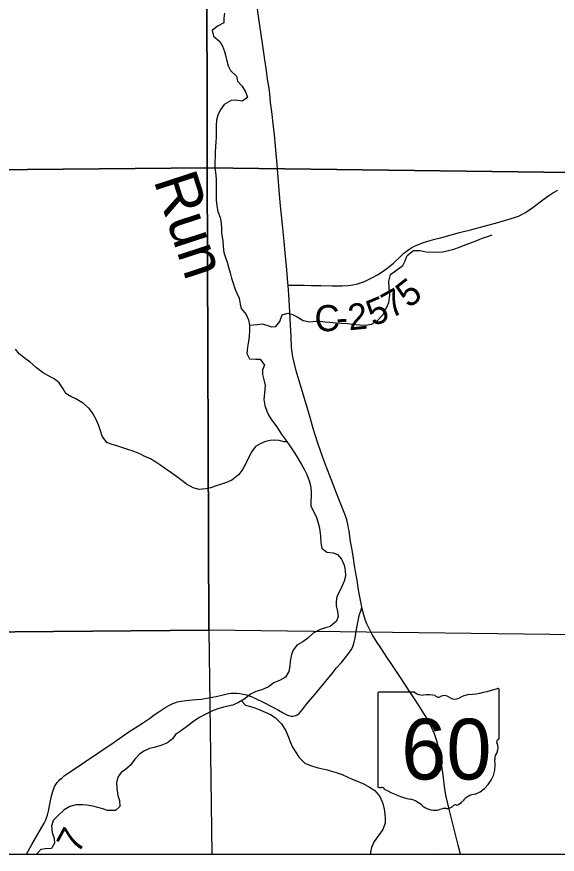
# Model space of a CAD drawing. Extents: x 0 to 34, y 0 to 22.
# Drawn here: x 2.657 to 3.831, y 18.268 to 20.086 of the extents above; entities that cross this region are included whole.
import ezdxf

# ---------------------------------------------------------------- set-up
doc = ezdxf.new("R2010")
doc.units = 0
for name, color, linetype in [('GM_X_County_Road', 7, 'Continuous'), ('GM_X_County_Road_Text', 7, 'Continuous'), ('GM_X_Interchange_Ramps', 7, 'Continuous'), ('GM_X_Major_River_Text', 7, 'Continuous'), ('GM_X_Section_Text', 7, 'Continuous'), ('GM_X_State_Route', 7, 'Continuous'), ('GM_X_Township_Road', 7, 'Continuous'), ('GM_X_Township_Road_Text', 7, 'Continuous'), ('GM_X_Township_Text', 7, 'Continuous'), ('SH_Text', 7, 'Continuous')]:
    doc.layers.add(name, color=color, linetype=linetype)

msp = doc.modelspace()

# ---------------------------------------------------------------- linework, layer by layer
at = {"layer": 'GM_X_County_Road'}
for p, q in [((3.5209, 18.6196), (3.4437, 18.6196)), ((3.7047, 18.5199), (3.7047, 18.6246)), ((3.4411, 18.6162), (3.4411, 18.4161)), ((3.7047, 18.5199), (3.7047, 18.5199))]:
    msp.add_line(p, q, dxfattribs=at)
for points in [[(3.4067, 18.8035), (3.4049, 18.8124), (3.4017, 18.8301), (3.3989, 18.8463), (3.3962, 18.863), (3.393, 18.882), (3.3908, 18.895), (3.3883, 18.9104), (3.3852, 18.9286), (3.3822, 18.9471), (3.3806, 18.9577), (3.3788, 18.9698), (3.3778, 18.9757), (3.376, 18.9848), (3.3736, 18.9937), (3.3708, 19.0025), (3.3654, 19.017), (3.3597, 19.0314), (3.3518, 19.0517), (3.3369, 19.0892), (3.327, 19.1154), (3.3173, 19.1416), (3.3103, 19.1622), (3.301, 19.1919), (3.2941, 19.2158), (3.2864, 19.2427), (3.2744, 19.2813), (3.2641, 19.3171), (3.2593, 19.3352), (3.2567, 19.3474), (3.2553, 19.3566), (3.254, 19.369), (3.2529, 19.3908), (3.251, 19.431), (3.2486, 19.4713), (3.2465, 19.5034), (3.2461, 19.5085), (3.2437, 19.5364), (3.2399, 19.5734), (3.2375, 19.5982), (3.2335, 19.6415), (3.2301, 19.6755), (3.2275, 19.7002), (3.2253, 19.7281), (3.2224, 19.765), (3.219, 19.8048), (3.2168, 19.8294), (3.2149, 19.8479), (3.2133, 19.8601), (3.2115, 19.8746), (3.2083, 19.9002), (3.2065, 19.9187), (3.205, 19.9309), (3.2027, 19.9463), (3.1984, 19.9739), (3.1957, 19.9923), (3.1915, 20.0231), (3.1846, 20.0724), (3.1759, 20.1339)], [(3.6208, 18.2679), (3.6156, 18.2875), (3.5967, 18.3628), (3.5924, 18.381), (3.5893, 18.3962), (3.5864, 18.4146), (3.583, 18.4392), (3.5788, 18.4699), (3.5763, 18.4852), (3.5739, 18.4973), (3.5709, 18.5093), (3.5682, 18.5182), (3.5651, 18.5269), (3.5615, 18.5355), (3.5562, 18.5466), (3.5474, 18.563), (3.5379, 18.5791), (3.5279, 18.5947), (3.5107, 18.6206), (3.4919, 18.6491), (3.4728, 18.6774), (3.461, 18.6956), (3.4493, 18.7138), (3.4372, 18.7318), (3.4288, 18.7449), (3.4223, 18.7579), (3.4176, 18.768), (3.4147, 18.7756), (3.4108, 18.7875), (3.4067, 18.8035)]]:
    msp.add_lwpolyline(points, dxfattribs=at)
for centre, radius, start, end in [((3.4441, 18.6166), 0.00305, 98.1301, 188.1301), ((3.5393, 18.6429), 0.0296, 231.6195, 271.1119), ((3.6108, 18.8925), 0.2796, 275.8445, 288.9065), ((3.7018, 18.625), 0.00294, 351.8621, 97.738), ((3.5491, 18.5073), 0.1064, 80.4867, 94.9883), ((3.5732, 18.6176), 0.00855, 219.7921, 297.1024), ((3.5858, 18.5945), 0.0178, 54.4667, 119.1411), ((3.6087, 18.6262), 0.0214, 233.8562, 294.8282), ((3.6465, 18.5585), 0.0563, 97.3462, 120.7689), ((3.704, 18.5122), 0.00454, 107.944, 210.337), ((3.6751, 18.499), 0.0273, 340.033, 23.6496), ((3.7016, 18.5195), 0.00314, 289.6038, 7.7341), ((3.6265, 18.4628), 0.0699, 292.3089, 8.9858), ((3.7152, 18.4761), 0.0198, 136.8065, 186.9296), ((3.4441, 18.4156), 0.00308, 171.9584, 258.3066), ((3.4446, 18.4361), 0.0235, 267.339, 280.6039), ((3.4494, 18.4045), 0.00848, 29.7484, 93.2717), ((3.5564, 18.5843), 0.2019, 240.4129, 257.1985), ((3.4962, 18.3262), 0.0632, 47.1842, 75.836), ((3.6074, 18.3967), 0.0226, 282.8732, 323.2771), ((3.656, 18.3599), 0.0383, 94.4031, 142.5768), ((3.5646, 18.4035), 0.0401, 230.7004, 286.2918), ((3.5877, 18.3343), 0.0329, 85.6951, 111.2099), ((3.5907, 18.3885), 0.0214, 268.777, 315.5493), ((3.61, 18.3692), 0.00601, 65.7517, 132.6484)]:
    msp.add_arc(centre, radius, start, end, dxfattribs=at)
at = {"layer": 'GM_X_County_Road_Text'}
for points in [[(3.108, 20.094), (3.1069, 20.0826), (3.1069, 20.0728), (3.0929, 20.0655), (3.0812, 20.056), (3.0843, 20.0435), (3.098, 20.0325), (3.1037, 20.0223), (3.108, 20.0102), (3.111, 19.9996), (3.1133, 19.9901), (3.1164, 19.9795), (3.121, 19.9692), (3.134, 19.9571), (3.1363, 19.9458), (3.1469, 19.9352), (3.1549, 19.9219), (3.1584, 19.9106), (3.1463, 19.9029), (3.133, 19.9048), (3.1228, 19.9043), (3.1077, 19.8956), (3.0986, 19.8834), (3.0938, 19.872), (3.0908, 19.8617), (3.0901, 19.8492), (3.0898, 19.8344), (3.0898, 19.8249), (3.0891, 19.8143), (3.0884, 19.8036), (3.088, 19.793), (3.0881, 19.7835), (3.0874, 19.7702), (3.0874, 19.7577), (3.0886, 19.7479), (3.0898, 19.7338), (3.0902, 19.7236), (3.0904, 19.6875), (3.0912, 19.6754), (3.0939, 19.6633), (3.0985, 19.6504), (3.1008, 19.6379), (3.1016, 19.6257), (3.102, 19.6151), (3.1044, 19.5999), (3.1056, 19.5874), (3.1071, 19.5745), (3.1106, 19.5635), (3.1137, 19.5533), (3.1168, 19.5423), (3.1206, 19.5302), (3.1237, 19.5184), (3.1268, 19.5078), (3.1306, 19.496), (3.1352, 19.4858), (3.1398, 19.4752), (3.1425, 19.4623), (3.1444, 19.4528), (3.1551, 19.4396), (3.1601, 19.4282), (3.1624, 19.4161), (3.1624, 19.4051), (3.1617, 19.3922)], [(3.1624, 19.4161), (3.1791, 19.418), (3.19, 19.4196), (3.2003, 19.4162), (3.2102, 19.4125), (3.22, 19.4137), (3.2287, 19.4247), (3.2335, 19.4391), (3.246, 19.4426), (3.2559, 19.4396), (3.2658, 19.4347), (3.2794, 19.4264), (3.2935, 19.4238), (3.3064, 19.425), (3.3158, 19.425), (3.3264, 19.4239), (3.3371, 19.4228), (3.35, 19.4217), (3.3621, 19.421), (3.3754, 19.4199), (3.386, 19.4185), (3.4023, 19.4174), (3.4152, 19.4167), (3.4273, 19.4186), (3.439, 19.4255), (3.4518, 19.4392), (3.4593, 19.4525), (3.4654, 19.4654), (3.4676, 19.4818), (3.466, 19.4969), (3.4655, 19.5117), (3.4685, 19.5262), (3.4957, 19.546), (3.5006, 19.5563), (3.5047, 19.5677), (3.5187, 19.5783), (3.5335, 19.5784), (3.546, 19.5754), (3.5687, 19.5747), (3.5816, 19.5759), (3.5949, 19.5783), (3.6062, 19.5813), (3.6187, 19.5859), (3.6308, 19.5909), (3.6414, 19.5948), (3.6566, 19.6005), (3.6664, 19.6047), (3.6796, 19.6093), (3.6898, 19.6128)], [(3.1617, 19.3922), (3.1606, 19.3819), (3.1584, 19.369), (3.157, 19.3546), (3.1627, 19.3432), (3.1763, 19.3429), (3.1858, 19.3426), (3.195, 19.3293), (3.1908, 19.3198), (3.1905, 19.3096), (3.1944, 19.2952), (3.1963, 19.2853), (3.1948, 19.269), (3.1938, 19.2553), (3.1957, 19.242), (3.1999, 19.2295), (3.2049, 19.2189), (3.2125, 19.2083), (3.2217, 19.1955), (3.2316, 19.1803), (3.24, 19.169), (3.2503, 19.1546), (3.2606, 19.1394), (3.2659, 19.1296), (3.2755, 19.1141), (3.2812, 19.1042), (3.2869, 19.0921), (3.2923, 19.0788), (3.295, 19.0682), (3.2966, 19.0553), (3.2966, 19.0447), (3.2955, 19.0344), (3.2959, 19.0238), (3.3005, 19.014), (3.3082, 18.9992), (3.3112, 18.9897), (3.3139, 18.9795), (3.3151, 18.97), (3.3167, 18.9583), (3.3175, 18.9438), (3.3194, 18.9321), (3.3308, 18.9238), (3.3441, 18.9219), (3.3536, 18.9189), (3.3624, 18.9083), (3.3681, 18.8958), (3.3704, 18.8845), (3.3712, 18.8716), (3.3682, 18.8609), (3.3637, 18.8503), (3.3585, 18.84), (3.3525, 18.8271), (3.3506, 18.8168), (3.351, 18.8073), (3.3534, 18.7948), (3.3549, 18.7838), (3.3516, 18.774), (3.338, 18.7621), (3.3277, 18.7594), (3.3149, 18.7548), (3.3009, 18.748), (3.2892, 18.7373), (3.2782, 18.7289), (3.2657, 18.7216), (3.2571, 18.711), (3.2537, 18.7015), (3.2511, 18.687), (3.2504, 18.6768), (3.2482, 18.6643), (3.2407, 18.6525), (3.2293, 18.6456), (3.2157, 18.6402), (3.204, 18.6315), (3.1896, 18.625), (3.176, 18.6211), (3.165, 18.6154), (3.1526, 18.6051), (3.1386, 18.5971), (3.1265, 18.5917), (3.1162, 18.589), (3.1064, 18.5874), (3.0939, 18.5836), (3.0822, 18.579), (3.0663, 18.571), (3.0538, 18.5645), (3.0417, 18.5565), (3.0289, 18.5465), (3.0145, 18.5362), (3.002, 18.5282), (2.9949, 18.5187), (2.9847, 18.5099), (2.9696, 18.5038), (2.9556, 18.4996), (2.9453, 18.4973), (2.9344, 18.4927), (2.9242, 18.4858), (2.9136, 18.474), (2.9034, 18.4603), (2.8932, 18.4519), (2.8834, 18.4454), (2.8762, 18.4352)], [(3.244, 19.1634), (3.2381, 19.1633), (3.2271, 19.1659), (3.2173, 19.1666), (3.2074, 19.1662), (3.1972, 19.1639), (3.1858, 19.1589), (3.1756, 19.1528), (3.1673, 19.1425), (3.1609, 19.1299), (3.1538, 19.1147), (3.1467, 19.1018), (3.1384, 19.0915), (3.124, 19.0801), (3.1127, 19.0747), (3.1017, 19.0713), (3.0881, 19.0667), (3.0782, 19.0636), (3.068, 19.0613), (3.0532, 19.0597), (3.0403, 19.0631), (3.0255, 19.0714), (3.0153, 19.0789), (3.0016, 19.0895), (2.9909, 19.097), (2.981, 19.1042), (2.9696, 19.1121), (2.9567, 19.1208), (2.9472, 19.1261), (2.9354, 19.1317), (2.9244, 19.137), (2.91, 19.1427), (2.9005, 19.146), (2.8876, 19.1505), (2.8743, 19.1547), (2.8622, 19.1584), (2.8527, 19.1618), (2.8424, 19.1754), (2.8386, 19.1868), (2.8355, 19.1982), (2.8305, 19.2103), (2.8217, 19.2258), (2.8141, 19.2356), (2.8019, 19.2466), (2.7856, 19.2568), (2.7742, 19.2617), (2.7639, 19.2681), (2.7575, 19.2783), (2.7494, 19.2916), (2.738, 19.2999), (2.7247, 19.307), (2.7141, 19.3131), (2.6997, 19.3236), (2.6856, 19.3372), (2.6761, 19.3437), (2.6624, 19.3542), (2.6544, 19.3644)], [(3.1452, 18.6009), (3.1537, 18.5918), (3.1647, 18.5884), (3.1742, 18.5854), (3.1849, 18.5813), (3.1966, 18.5764), (3.2084, 18.5711), (3.2183, 18.5651), (3.232, 18.5507), (3.2411, 18.536), (3.2473, 18.5223), (3.2511, 18.5121), (3.2557, 18.5007), (3.2622, 18.4905), (3.2706, 18.4776), (3.2828, 18.4655), (3.2953, 18.4607), (3.3089, 18.4565), (3.3184, 18.4539), (3.3309, 18.4509), (3.3408, 18.4483), (3.3511, 18.4457), (3.364, 18.4408), (3.3761, 18.4355), (3.3856, 18.431), (3.3951, 18.4273), (3.4088, 18.4212), (3.4213, 18.4152), (3.4346, 18.4065), (3.4456, 18.3933), (3.4518, 18.3778), (3.4548, 18.366), (3.4564, 18.3546), (3.4572, 18.3448), (3.4569, 18.3353), (3.4524, 18.3216), (3.4426, 18.3083), (3.4335, 18.2953), (3.4275, 18.2824), (3.4253, 18.2722), (3.4253, 18.2679)], [(2.8762, 18.4352), (2.8736, 18.423), (2.8741, 18.4109), (2.8768, 18.3957), (2.8799, 18.3847), (2.8811, 18.3718), (2.8712, 18.3627), (2.8542, 18.363), (2.8439, 18.3663), (2.8333, 18.3693), (2.8223, 18.372), (2.8094, 18.3746), (2.7996, 18.3749), (2.7863, 18.3748), (2.7719, 18.3714), (2.7602, 18.3645), (2.7459, 18.3515), (2.736, 18.3409), (2.7323, 18.3287), (2.7335, 18.3154), (2.7381, 18.3018), (2.7389, 18.2919), (2.7321, 18.2805), (2.7189, 18.2797), (2.709, 18.2782), (2.6999, 18.2679)]]:
    msp.add_lwpolyline(points, dxfattribs=at)
at = {"layer": 'GM_X_Interchange_Ramps'}
msp.add_lwpolyline([(2.6776, 18.2679), (2.6779, 18.2684), (2.6899, 18.2894), (2.7085, 18.3213), (2.7164, 18.3353), (2.72, 18.3424), (2.7219, 18.3472), (2.7234, 18.3524), (2.7256, 18.3615), (2.7288, 18.3767), (2.7326, 18.3948), (2.7351, 18.4042), (2.7374, 18.4108), (2.7392, 18.4148), (2.7418, 18.4194), (2.7446, 18.4236), (2.748, 18.4272), (2.7507, 18.43), (2.7554, 18.4339), (2.7602, 18.4379), (2.7673, 18.4431), (2.7883, 18.4572), (2.8064, 18.4691), (2.8372, 18.4901), (2.8684, 18.5114), (2.8985, 18.5319), (2.9142, 18.5421), (2.9321, 18.554), (2.9451, 18.5627), (2.9557, 18.5702), (2.9654, 18.5768), (2.9811, 18.5869), (2.989, 18.5916), (2.9945, 18.5944), (3.0002, 18.5967), (3.006, 18.5985), (3.0151, 18.6005), (3.0242, 18.6018), (3.0387, 18.6031), (3.0576, 18.6048), (3.0744, 18.6076), (3.0899, 18.6103), (3.1079, 18.6145), (3.1168, 18.6166), (3.1227, 18.6173), (3.1291, 18.6177), (3.1353, 18.6173), (3.1415, 18.6167), (3.1481, 18.6157), (3.156, 18.6137), (3.1658, 18.6105), (3.1904, 18.5988), (3.2149, 18.5867), (3.2255, 18.5809), (3.2345, 18.5757), (3.2425, 18.5714), (3.2472, 18.5693), (3.2506, 18.5683), (3.2535, 18.5679), (3.2567, 18.5678), (3.2599, 18.5682), (3.2629, 18.5693), (3.2658, 18.5706), (3.2685, 18.5723), (3.271, 18.5744), (3.2733, 18.577), (3.2778, 18.5823), (3.2867, 18.5935), (3.3045, 18.6149), (3.3146, 18.6271), (3.342, 18.6604), (3.3518, 18.6726), (3.3622, 18.6844), (3.3739, 18.6987), (3.3801, 18.7064), (3.3835, 18.7119), (3.3862, 18.717), (3.3886, 18.7231), (3.3901, 18.7283), (3.3922, 18.7373), (3.3945, 18.7524), (3.3969, 18.7675), (3.3998, 18.7815), (3.4015, 18.788), (3.4045, 18.7963), (3.4067, 18.8035)], dxfattribs=at)
at = {"layer": 'GM_X_State_Route'}
for points in [[(2.0472, 20.7772), (3.0692, 20.7682), (3.0705, 19.7579), (2.0531, 19.7487)], [(3.0692, 20.7682), (4.0731, 20.7603), (4.0736, 20.7285), (4.0835, 19.7451), (3.0705, 19.7579)], [(2.0531, 19.7487), (3.0705, 19.7579), (3.0743, 18.754), (2.0616, 18.746)], [(3.0705, 19.7579), (4.0835, 19.7451), (4.0839, 19.7307), (4.0999, 18.7413), (3.0743, 18.754)]]:
    msp.add_lwpolyline(points, close=True, dxfattribs=at)
msp.add_lwpolyline([(2.0795, 18.2679), (2.0616, 18.746), (3.0743, 18.754), (3.0806, 18.2679)], dxfattribs=at)
at = {"layer": 'GM_X_Township_Road'}
msp.add_lwpolyline([(3.2465, 19.5034), (3.2523, 19.5034), (3.265, 19.5032), (3.281, 19.5031), (3.2962, 19.5027), (3.3173, 19.5025), (3.342, 19.502), (3.3637, 19.5021), (3.3772, 19.5028), (3.3869, 19.5039), (3.3947, 19.5057), (3.4037, 19.5081), (3.4126, 19.5113), (3.4209, 19.5153), (3.4295, 19.5197), (3.4403, 19.5258), (3.4509, 19.5322), (3.4611, 19.5394), (3.4684, 19.5452), (3.4754, 19.5514), (3.4911, 19.5664), (3.4981, 19.5725), (3.5054, 19.5782), (3.5131, 19.5833), (3.5211, 19.5878), (3.5295, 19.5917), (3.5382, 19.5951), (3.5502, 19.5986), (3.5651, 19.6028), (3.58, 19.607), (3.6186, 19.6174), (3.6457, 19.6241), (3.6723, 19.6315), (3.702, 19.6396), (3.7234, 19.6456), (3.7382, 19.6501), (3.7469, 19.6533), (3.7526, 19.6558), (3.7609, 19.6601), (3.7687, 19.6651), (3.7788, 19.6724), (3.7995, 19.6885), (3.8124, 19.6979), (3.8214, 19.7037), (3.8322, 19.7095)], dxfattribs=at)
at = {"layer": 'SH_Text'}
msp.add_line((2.0719, 18.2679), (4.4056, 18.2679), dxfattribs=at)

# ---------------------------------------------------------------- texts
at = {"layer": 'GM_X_County_Road'}
msp.add_text('60', height=0.13184, dxfattribs=at).set_placement((3.4921, 18.4302))
at = {"layer": 'GM_X_Major_River_Text'}
msp.add_text('60', height=0.000189, rotation=0, dxfattribs=at).set_placement((3.5635, 18.2723))
for s, p in [('s', (3.6112, 18.2861)), ('r', (3.6111, 18.2861))]:
    msp.add_text(s, height=0.000189, dxfattribs=at).set_placement(p)
at = {"layer": 'GM_X_Section_Text'}
for s, rotation, p in [('5', 37.883, (3.5085, 19.4519)), ('7', 29.1496, (3.47, 19.4296)), ('5', 22.5941, (3.4313, 19.4131)), ('C', 1.9245, (3.3048, 19.4024)), ('2', 5.746, (3.3789, 19.4051)), ('-', 2.0553, (3.3516, 19.404))]:
    msp.add_text(s, height=0.0568, rotation=rotation, dxfattribs=at).set_placement(p)
at = {"layer": 'GM_X_Township_Road_Text'}
msp.add_text('Run', height=0.09472, rotation=288.0815, dxfattribs=at).set_placement((2.9538, 19.7311))
at = {"layer": 'GM_X_Township_Text'}
msp.add_text('7', height=0.0568, rotation=61.3091, dxfattribs=at).set_placement((2.7904, 18.2667))

doc.saveas('drawing.dxf')
